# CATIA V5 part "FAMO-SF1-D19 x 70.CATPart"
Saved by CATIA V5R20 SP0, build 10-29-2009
Part number: FAMO-SF1-D19 x 70
Definition: NONE
Nomenclature: FAMO-SF1-D19 x 70
Source: Unknown
Description: FAMO-SF1-D19 x 70
Bounding box of the stored display mesh (mm): x -43 to 27, y -17 to 17, z -17 to 17
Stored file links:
  C:\Users\Utente\Desktop\IO LAVORO\3D X SITO CF\X SITO\FAMO\FAMO-SF1-D19 x 70.CATPart
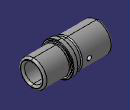
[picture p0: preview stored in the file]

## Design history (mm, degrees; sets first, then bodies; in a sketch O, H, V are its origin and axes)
Body1 "FAMO-SF1-D19 x 70" (main body)
  Solid1: solid without history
